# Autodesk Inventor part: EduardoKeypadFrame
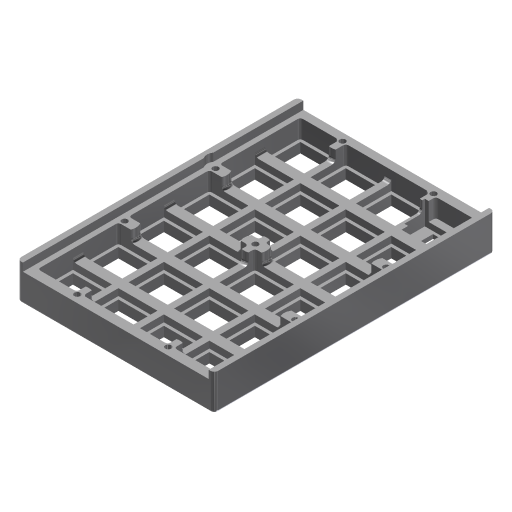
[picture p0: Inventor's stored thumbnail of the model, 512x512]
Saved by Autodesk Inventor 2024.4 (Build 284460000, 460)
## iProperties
Created: 2026-02
Part Number: EduardoKeypadFrame
Material: Standard
Document SubType Name: Modeling
Designer: offt
Density: 1 g/cm^3
Appearance: Vorgabe
Author: offt
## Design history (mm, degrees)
derived "frame.ipt"
node "Volumenkörper"
node "Flächenkörper"
feature "Volumenkörper1::frame.ipt" dims "d0" = 10
tag "Bezeichnung1"
node "Volumenkörper1"
